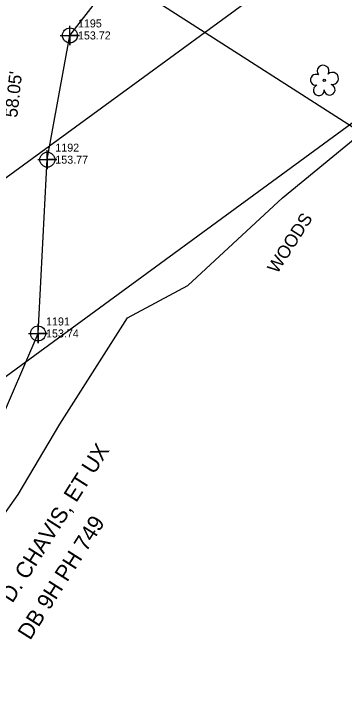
# Model space of a CAD drawing. Extents: x 1840200 to 1849051, y 348278 to 353012.
# Drawn here: x 1844736.7 to 1844839.8, y 350387.3 to 350604.9 of the extents above; entities that cross this region are included whole.
import ezdxf

# ---------------------------------------------------------------- set-up
doc = ezdxf.new("R2010")
doc.units = 0
for name, color, linetype in [('Default', 7, 'Continuous'), ('Exist Horizontal Baseline Alignment Station Label', 7, 'Continuous'), ('Exist Hydro Jurisdictional Stream or Body of Water', 7, 'Continuous'), ('Exist Hydro Stream or Body of Water Cogo Elevation', 7, 'Continuous'), ('Exist Hydro Stream or Body of Water Cogo Number', 7, 'Continuous'), ('Exist Hydro Stream or Body of Water Cogo Point CELL', 7, 'Continuous'), ('Exist Property Deed Book Text', 7, 'Continuous'), ('Exist Property Line', 7, 'Continuous'), ('Exist Property Line Text', 7, 'Continuous'), ('Exist Property Owner Text', 7, 'Continuous'), ('Exist Right of Way Easement Line', 7, 'Continuous'), ('Exist Vegetation Tree CELL', 7, 'Continuous'), ('Exist Vegetation Woods Line', 7, 'Continuous'), ('Exist Vegetation Woods Line Text', 7, 'Continuous')]:
    doc.layers.add(name, color=color, linetype=linetype)

# ---------------------------------------------------------------- blocks, each defined once
blk = doc.blocks.new('EXIST HYDRO STREAM OR BODY OF WATER COGO POINT')
at = {"layer": 'Exist Hydro Stream or Body of Water Cogo Point CELL'}
blk.add_lwpolyline([(-0.06, 0), (0.06, 0), (0, 0), (0, -0.06), (0, 0.06)], dxfattribs=at)
blk.add_circle((0, 0), 0.0469, dxfattribs=at)
blk = doc.blocks.new('EXIST VEGETATION TREE')
at = {"layer": 'Exist Vegetation Tree CELL'}
blk.add_line((0, 0), (0, 0), dxfattribs=at)
blk.add_circle((0, 0), 0.00652, dxfattribs=at)
for centre, radius, start, end in [((-0.0077, 0.0575), 0.0371, 330.1651, 219.7134), ((0.051, 0.0118), 0.038, 257.1011, 134.1999), ((-0.0521, 0.0031), 0.0345, 62.6636, 279.3457), ((-0.0341, -0.0624), 0.0338, 111.5671, 6.231), ((0.0335, -0.058), 0.034, 181.2822, 74.56)]:
    blk.add_arc(centre, radius, start, end, dxfattribs=at)

msp = doc.modelspace()

# ---------------------------------------------------------------- linework, layer by layer
at = {"layer": 'Exist Horizontal Baseline Alignment Station Label'}
msp.add_line((1844672.71, 350678.49), (1844914.65, 350523.26), dxfattribs=at)
at = {"layer": 'Exist Hydro Jurisdictional Stream or Body of Water'}
msp.add_lwpolyline([(1844685.43, 350438.65), (1844695.82, 350440.85), (1844718.62, 350445.67), (1844744.24, 350505.15), (1844747.14, 350559.4), (1844754.2, 350598.17), (1844784.35, 350637.07), (1844806.33, 350724.3), (1844791.7, 350751.83), (1844775.16, 350786.41), (1844754.3, 350810.58), (1844752.94, 350811.45)], dxfattribs=at)
at = {"layer": 'Exist Property Line'}
msp.add_line((1844729.25, 350550.14), (1845268.47, 350944.43), dxfattribs=at)
at = {"layer": 'Exist Right of Way Easement Line'}
msp.add_line((1844458.92, 350290.53), (1845297.98, 350904.07), dxfattribs=at)
at = {"layer": 'Exist Vegetation Woods Line'}
for points in [[(1844820.52, 350547.53), (1844856.07, 350576.6), (1844904.56, 350610.06), (1844930.4, 350621.75), (1844946.86, 350637.64), (1844961.25, 350655.71), (1844978.34, 350668.76), (1845022.23, 350698.9)], [(1844725.81, 350375.09), (1844723.83, 350391.87), (1844704.01, 350403.62), (1844674.19, 350422.02), (1844646.86, 350447.83), (1844631.85, 350456.73), (1844628.32, 350465.12), (1844629.22, 350467.36), (1844631.58, 350469.97), (1844642.32, 350464.41), (1844654.55, 350456.45), (1844686.67, 350435.73), (1844700.19, 350427.71), (1844720.05, 350429.54), (1844738, 350454.9), (1844751, 350476.83), (1844772.13, 350510.05), (1844790.99, 350520.11), (1844820.52, 350547.53)]]:
    msp.add_lwpolyline(points, dxfattribs=at)

# ---------------------------------------------------------------- block references
at = {"layer": 'Default', "xscale": 50, "yscale": 50}
msp.add_blockref('EXIST VEGETATION TREE', (1844833.62, 350584.16), dxfattribs=at)
at = {"layer": 'Exist Hydro Stream or Body of Water Cogo Point CELL', "xscale": 50, "yscale": 50}
for p in [(1844754.2, 350598.17), (1844747.14, 350559.4), (1844744.24, 350505.15)]:
    msp.add_blockref('EXIST HYDRO STREAM OR BODY OF WATER COGO POINT', p, dxfattribs=at)

# ---------------------------------------------------------------- texts
at = {"layer": 'Exist Hydro Stream or Body of Water Cogo Elevation'}
for s, p in [('153.72', (1844756.7, 350596.92)), ('153.77', (1844749.64, 350558.15)), ('153.74', (1844746.74, 350503.9))]:
    msp.add_text(s, height=2.5, dxfattribs=at).set_placement(p)
at = {"layer": 'Exist Hydro Stream or Body of Water Cogo Number'}
for s, p in [('1195', (1844756.7, 350600.67)), ('1192', (1844749.64, 350561.9)), ('1191', (1844746.74, 350507.65))]:
    msp.add_text(s, height=2.5, dxfattribs=at).set_placement(p)
at = {"layer": 'Exist Property Deed Book Text'}
msp.add_text('DB 9H PH 749', height=5, rotation=57.5703, dxfattribs=at).set_placement((1844741.76, 350409.18))
at = {"layer": 'Exist Property Line Text'}
msp.add_text("58.05'", height=4, rotation=83.7153, dxfattribs=at).set_placement((1844737.73, 350572.4))
at = {"layer": 'Exist Property Owner Text'}
msp.add_text('RANDY D. CHAVIS, ET UX', height=5, rotation=57.5703, dxfattribs=at).set_placement((1844722.68, 350399.45))
at = {"layer": 'Exist Vegetation Woods Line Text'}
msp.add_text('WOODS', height=4, rotation=57.4041, dxfattribs=at).set_placement((1844818.92, 350523.58))

doc.saveas('drawing.dxf')
